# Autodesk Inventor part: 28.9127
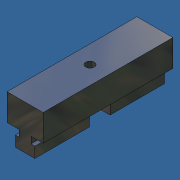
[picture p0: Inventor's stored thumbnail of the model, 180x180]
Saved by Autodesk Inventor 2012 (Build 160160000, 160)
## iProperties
Created: 2007-06
Part Number: 28.9127
Material: UHMW, Black
Document SubType Name: Modeling
Designer: Andy Moles
Density: 0.94 g/cm^3
Description: L = 3.543", MILL TO 28.9127
Stock Number: 22.1089 SLIDE BAR 23
Mass: 48.7974 g
Surface Area: 123.535 cm^2
Volume: 51.9121 cm^3
Vendor: F
Author: Andy Moles
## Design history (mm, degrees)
sketch "Sketch1"
  geometry: L1 (4.1, -4.6)-(6.75, -4.6); L2 (4.1, 0)-(4.1, -4.6); L3 (12.5, 0)-(4.1, 0); L4 (12.5, 18.5)-(12.5, 0); L5 (-12.5, 18.5)-(12.5, 18.5); L6 (-12.5, 0)-(-12.5, 18.5); L7 (-4.1, 0)-(-12.5, 0); L8 (-4.1, -4.6)-(-4.1, 0); L9 (-6.75, -4.6)-(-4.1, -4.6); L10 (-6.75, -12)-(-6.75, -4.6); L11 (6.75, -12)-(-6.75, -12); L12 (6.75, -4.6)-(6.75, -12); 4 further points
  constraints: 24 end point, 5 equal length, 3 horizontal, 3 vertical, 2 horizontal alignment, 2 midpoint, 2 vertical alignment
  dimensions: "d2" = 7.4 distance between parallel lines of L1 L11; "d3" = 13.5 distance of L11.start L10.start; "d4" = 12 distance between parallel lines of L11 L7; "d5" = 4.10001 distance from line of L8 point (0, 0); "d6" = 25 distance of L5.start L4.start; "d7" = 18.5 distance between parallel lines of L3 L5
extrude "Extrusion1" new body sketch "Sketch1" stored distance "d0" = 90; taper "d1" = 0 deg
sketch "Sketch2"
  geometry: L1 (0, -90)-(0, 0) reference; L2 (13.5, -90)-(13.5, 0) reference; L3 (13.5, -37.863)-(0, -37.863); L4 (0, -37.863)-(0, -52.137); L5 (0, -52.137)-(13.5, -52.137); L6 (13.5, -52.137)-(13.5, -37.863); 2 further points
  constraints: 8 end point, 2 parallel, 2 point on line, 1 horizontal, 1 horizontal alignment, 1 midpoint, 1 perpendicular
  dimensions: "d8" = 14.2748 distance between parallel lines of L5 L3
extrude "Extrusion2" cut sketch "Sketch2" distance "d9" = 7.62; taper "d10" = 0 deg
sketch "Sketch3"
  geometry: C1 r 3 at (6.75, -45); 1 further point
  constraints: 1 centre point, 1 coincident
  dimensions: "d11" = 6 diameter of C1
extrude "Extrusion3" cut sketch "Sketch3" stored distance "d12" = 7.62; taper "d13" = 0 deg
body "Solid1"
